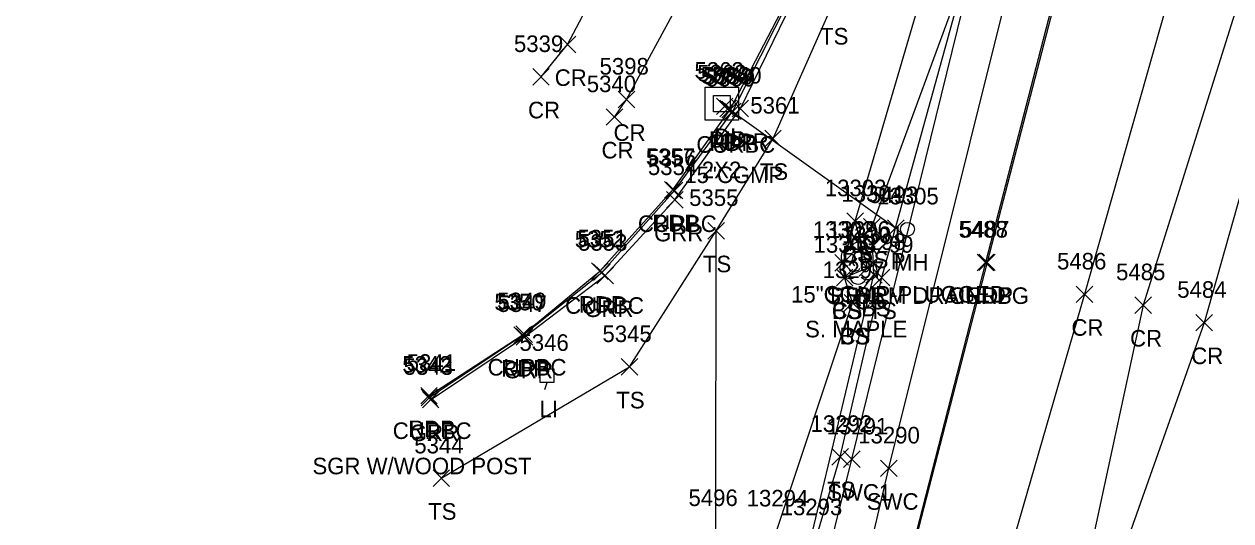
# Model space of a CAD drawing. Extents: x 1462089 to 1464015, y 730534 to 736144.
# Drawn here: x 1462338.4 to 1462484, y 730971.5 to 731031.4 of the extents above; entities that cross this region are included whole.
import ezdxf

# ---------------------------------------------------------------- set-up
doc = ezdxf.new("R2010")
doc.units = 0
for name, color, linetype in [('D_A', 7, 'Continuous'), ('D_C', 7, 'Continuous'), ('D_I', 7, 'Continuous'), ('D_TIC', 7, 'Continuous'), ('DCP', 7, 'Continuous'), ('DS', 7, 'Continuous'), ('L_A', 7, 'Continuous'), ('L_C', 7, 'Continuous'), ('L_I', 7, 'Continuous'), ('L_TIC', 7, 'Continuous'), ('LELB', 7, 'Continuous'), ('LTD', 7, 'Continuous'), ('P_A', 7, 'Continuous'), ('P_I', 7, 'Continuous'), ('P_TIC', 7, 'Continuous'), ('PET', 7, 'Continuous'), ('PRC', 7, 'Continuous'), ('R_A', 7, 'Continuous'), ('R_C', 7, 'Continuous'), ('R_I', 7, 'Continuous'), ('R_TIC', 7, 'Continuous'), ('RC', 7, 'Continuous'), ('RGR', 7, 'Continuous'), ('RSW', 7, 'Continuous'), ('U_A', 7, 'Continuous'), ('U_C', 7, 'Continuous'), ('U_I', 7, 'Continuous'), ('ULP', 7, 'Continuous'), ('UUMH', 7, 'Continuous')]:
    doc.layers.add(name, color=color, linetype=linetype)

msp = doc.modelspace()

# ---------------------------------------------------------------- linework, layer by layer
at = {"layer": 'D_TIC'}
for points in [[(1462421.97, 731020.53), (1462423.97, 731022.53)], [(1462423.97, 731020.53), (1462421.97, 731022.53)], [(1462422.39, 731020.27), (1462424.39, 731022.27)], [(1462424.39, 731020.27), (1462422.39, 731022.27)], [(1462442.63, 731005.85), (1462444.63, 731007.85)], [(1462444.63, 731005.85), (1462442.63, 731007.85)]]:
    msp.add_lwpolyline(points, dxfattribs=at)
at = {"layer": 'DCP'}
msp.add_lwpolyline([(1462423.39, 731021.27), (1462443.63, 731006.85)], dxfattribs=at)
at = {"layer": 'DS'}
for p, q in [((1462420.63, 731023.85), (1462424.63, 731023.85)), ((1462420.63, 731019.85), (1462420.63, 731023.85)), ((1462424.63, 731023.85), (1462424.63, 731019.85)), ((1462421.63, 731020.85), (1462421.63, 731022.85)), ((1462421.63, 731022.85), (1462423.63, 731022.85)), ((1462423.63, 731022.85), (1462423.63, 731020.85)), ((1462423.63, 731020.85), (1462421.63, 731020.85)), ((1462422.63, 731021.86), (1462422.63, 731021.86)), ((1462422.63, 731021.86), (1462422.63, 731021.86)), ((1462424.63, 731019.85), (1462420.63, 731019.85))]:
    msp.add_line(p, q, dxfattribs=at)
at = {"layer": 'L_TIC'}
for points in [[(1462427.8, 731016.65), (1462429.8, 731018.65)], [(1462429.8, 731016.65), (1462427.8, 731018.65)], [(1462437.72, 731006.68), (1462439.72, 731008.68)], [(1462439.72, 731006.68), (1462437.72, 731008.68)], [(1462437.72, 731006.68), (1462439.72, 731008.68)], [(1462439.72, 731006.68), (1462437.72, 731008.68)], [(1462439.72, 731006.01), (1462441.72, 731008.01)], [(1462441.72, 731006.01), (1462439.72, 731008.01)], [(1462420.94, 731005.51), (1462422.94, 731007.51)], [(1462422.94, 731005.51), (1462420.94, 731007.51)], [(1462436.25, 731001.66), (1462438.25, 731003.66)], [(1462438.25, 731001.66), (1462436.25, 731003.66)], [(1462436.44, 730999.87), (1462438.44, 731001.87)], [(1462438.44, 730999.87), (1462436.44, 731001.87)], [(1462436.44, 730999.87), (1462438.44, 731001.87)], [(1462438.44, 730999.87), (1462436.44, 731001.87)], [(1462439.2, 731001.04), (1462441.2, 731003.04)], [(1462441.2, 731001.04), (1462439.2, 731003.04)], [(1462439.98, 731000.2), (1462441.98, 731002.2)], [(1462441.98, 731000.2), (1462439.98, 731002.2)], [(1462439.98, 731000.2), (1462441.98, 731002.2)], [(1462441.98, 731000.2), (1462439.98, 731002.2)], [(1462440.91, 730999.87), (1462442.91, 731001.87)], [(1462442.91, 730999.87), (1462440.91, 731001.87)], [(1462437.38, 730996.81), (1462439.38, 730998.81)], [(1462439.38, 730996.81), (1462437.38, 730998.81)], [(1462437.38, 730996.81), (1462439.38, 730998.81)], [(1462439.38, 730996.81), (1462437.38, 730998.81)], [(1462410.48, 730989.09), (1462412.48, 730991.09)], [(1462412.48, 730989.09), (1462410.48, 730991.09)], [(1462435.91, 730978.25), (1462437.91, 730980.25)], [(1462437.91, 730978.25), (1462435.91, 730980.25)], [(1462387.78, 730975.66), (1462389.78, 730977.66)], [(1462389.78, 730975.66), (1462387.78, 730977.66)]]:
    msp.add_lwpolyline(points, dxfattribs=at)
at = {"layer": 'LELB'}
for points in [[(1462388.78, 730976.66), (1462411.48, 730990.09), (1462421.94, 731006.51), (1462428.8, 731017.65), (1462436.07, 731033.98), (1462445.93, 731054.5), (1462454.8, 731072.36), (1462455.33, 731073.48), (1462460.84, 731086.83), (1462466.01, 731088.73), (1462468.93, 731104.02), (1462472.78, 731103.78), (1462475.18, 731100.17)], [(1462438.38, 730997.81), (1462437.44, 731000.87), (1462440.2, 731002.04), (1462438.72, 731007.68), (1462447.67, 731038.22), (1462450.05, 731039.02), (1462449.7, 731045.42), (1462457.74, 731068.03), (1462468.26, 731085.52), (1462472.82, 731091.07), (1462474.19, 731089.34)], [(1462427.16, 730950.62), (1462433.31, 730969.2), (1462440.98, 731001.2), (1462440.72, 731007.01), (1462452.3, 731038.49), (1462460.27, 731066.27)], [(1462429.66, 730954.76), (1462436.91, 730979.25), (1462441.91, 731000.87), (1462452.3, 731038.49)], [(1462437.44, 731000.87), (1462437.25, 731002.66), (1462438.72, 731007.68)], [(1462421.91, 730970.31), (1462421.94, 731006.51)], [(1462419.91, 730951.53), (1462429.21, 730970.26), (1462438.38, 730997.81), (1462440.98, 731001.2)]]:
    msp.add_lwpolyline(points, dxfattribs=at)
at = {"layer": 'LTD'}
msp.add_line((1462439.09, 731002.66), (1462439.09, 731002.66), dxfattribs=at)
msp.add_line((1462439.09, 731002.66), (1462439.09, 731002.66), dxfattribs=at)
msp.add_arc((1462439.14, 731004.1), 1.05, 335.5272, 180.9563, dxfattribs=at)
for centre, major_axis, ratio, start_param, end_param in [((1462438.3, 731003.33), (1.21, -0.51), 0.895232, 1.570796, 4.712389), ((1462438.88, 731003.12), (-0.208, -0.792), 0.645439, 3.141593, 6.283185), ((1462439.59, 731002.5), (-0.5, 0.667), 0.989748, 3.141593, 6.283185), ((1462440.13, 731003.25), (-1.14, -0.48), 0.949671, 1.570796, 4.712389), ((1462438.01, 731001.95), (0.58, -1.04), 0.959034, 3.141593, 6.283185), ((1462438.63, 731001.91), (-0.625, -0.083), 0.423636, 0, 3.141593), ((1462440.09, 731001.83), (-1.09, 0.79), 0.841452, 1.570796, 4.712389), ((1462439.09, 731001.16), (0.26, 1.06), 0.942809, 1.570796, 4.712389)]:
    msp.add_ellipse(centre, major_axis=major_axis, ratio=ratio, start_param=start_param, end_param=end_param, dxfattribs=at)
at = {"layer": 'P_TIC'}
for points in [[(1462403.02, 731027.99), (1462405.02, 731029.99)], [(1462405.02, 731027.99), (1462403.02, 731029.99)], [(1462399.81, 731024.08), (1462401.81, 731026.08)], [(1462401.81, 731024.08), (1462399.81, 731026.08)], [(1462410.13, 731021.36), (1462412.13, 731023.36)], [(1462412.13, 731021.36), (1462410.13, 731023.36)], [(1462408.68, 731019.24), (1462410.68, 731021.24)], [(1462410.68, 731019.24), (1462408.68, 731021.24)], [(1462422.63, 731020.14), (1462424.63, 731022.14)], [(1462424.63, 731020.14), (1462422.63, 731022.14)], [(1462415.71, 731010.45), (1462417.71, 731012.45)], [(1462417.71, 731010.45), (1462415.71, 731012.45)], [(1462453.62, 731001.71), (1462455.62, 731003.71)], [(1462455.62, 731001.71), (1462453.62, 731003.71)], [(1462406.89, 731000.63), (1462408.89, 731002.63)], [(1462408.89, 731000.63), (1462406.89, 731002.63)], [(1462465.38, 730997.85), (1462467.38, 730999.85)], [(1462467.38, 730997.85), (1462465.38, 730999.85)], [(1462472.45, 730996.55), (1462474.45, 730998.55)], [(1462474.45, 730996.55), (1462472.45, 730998.55)], [(1462479.83, 730994.43), (1462481.83, 730996.43)], [(1462481.83, 730994.43), (1462479.83, 730996.43)], [(1462397.52, 730992.91), (1462399.52, 730994.91)], [(1462399.52, 730992.91), (1462397.52, 730994.91)], [(1462386.29, 730985.62), (1462388.29, 730987.62)], [(1462388.29, 730985.62), (1462386.29, 730987.62)]]:
    msp.add_lwpolyline(points, dxfattribs=at)
at = {"layer": 'PET'}
for points in [[(1462387.29, 730986.62), (1462398.52, 730993.91), (1462407.89, 731001.63), (1462416.71, 731011.45), (1462423.63, 731021.14), (1462432.28, 731037.78), (1462439.01, 731056.63), (1462451.5, 731091.34), (1462455.92, 731100.01), (1462464.31, 731107.07), (1462468.29, 731108.58), (1462472.93, 731107.75)], [(1462468.33, 731055.46), (1462454.62, 731002.71), (1462439.37, 730943.54), (1462426.72, 730893.88), (1462414.13, 730848.03), (1462402.67, 730810.27), (1462391.12, 730771.79), (1462384.96, 730750.7), (1462383.45, 730746.12), (1462378.84, 730730.43)]]:
    msp.add_lwpolyline(points, dxfattribs=at)
at = {"layer": 'PRC'}
for points in [[(1462761.02, 731958.42), (1462747.81, 731917.01), (1462738.76, 731883.17), (1462729.11, 731854.95), (1462715.07, 731806.48), (1462712.12, 731796.98), (1462698.11, 731749.33), (1462686.28, 731711.96), (1462673.04, 731665.23), (1462661.99, 731629.57), (1462648.47, 731585.76), (1462633.36, 731535.92), (1462617.82, 731486.9), (1462603.28, 731439.32), (1462592.21, 731404.81), (1462578.75, 731359.84), (1462563.85, 731311.63), (1462546.16, 731252.05), (1462529.31, 731193.32), (1462512.83, 731138.46), (1462500.46, 731089.18), (1462489.91, 731049.97), (1462473.45, 730997.55), (1462460.79, 730938.78)], [(1462502.24, 731140.65), (1462491.59, 731093.41), (1462481.41, 731051.89), (1462466.38, 730998.85), (1462449.74, 730941.33), (1462438.11, 730890.41), (1462425.45, 730844.2), (1462414.38, 730806.64), (1462401.13, 730755.95), (1462392.12, 730727.26), (1462378.76, 730682.13), (1462374.56, 730668.66), (1462358.3, 730624.57), (1462349.45, 730590.21), (1462338.44, 730561.09)], [(1462522.11, 731136.27), (1462509.01, 731086.5), (1462495.84, 731048.68), (1462480.83, 730995.43), (1462460.79, 730938.78), (1462449.01, 730886.81), (1462435.47, 730841.1), (1462424.6, 730802.23), (1462409.98, 730750.74), (1462401.88, 730724.37), (1462388, 730678.77), (1462384.49, 730666.35), (1462369.1, 730623.58), (1462360.68, 730585), (1462348.49, 730557.7)], [(1462400.81, 731025.08), (1462404.02, 731028.99), (1462414.27, 731048.41), (1462425.15, 731083.36), (1462432.01, 731107.16), (1462441.86, 731124.76)], [(1462409.68, 731020.24), (1462411.13, 731022.36), (1462424.24, 731046.53), (1462435.58, 731081.11), (1462442.07, 731100.85), (1462450.24, 731114.13), (1462458.36, 731120.68), (1462472.22, 731125.09), (1462482.97, 731125.14)]]:
    msp.add_lwpolyline(points, dxfattribs=at)
at = {"layer": 'R_TIC'}
for points in [[(1462423.86, 731020.27), (1462425.86, 731022.27)], [(1462425.86, 731020.27), (1462423.86, 731022.27)], [(1462422.96, 731019.93), (1462424.96, 731021.93)], [(1462424.96, 731019.93), (1462422.96, 731021.93)], [(1462415.92, 731010.37), (1462417.92, 731012.37)], [(1462417.92, 731010.37), (1462415.92, 731012.37)], [(1462415.96, 731009.24), (1462417.96, 731011.24)], [(1462417.96, 731009.24), (1462415.96, 731011.24)], [(1462453.45, 731001.69), (1462455.45, 731003.69)], [(1462455.45, 731001.69), (1462453.45, 731003.69)], [(1462407.14, 731000.5), (1462409.14, 731002.5)], [(1462409.14, 731000.5), (1462407.14, 731002.5)], [(1462407.54, 731000.11), (1462409.54, 731002.11)], [(1462409.54, 731000.11), (1462407.54, 731002.11)], [(1462397.78, 730993.05), (1462399.78, 730995.05)], [(1462399.78, 730993.05), (1462397.78, 730995.05)], [(1462397.82, 730992.72), (1462399.82, 730994.72)], [(1462399.82, 730992.72), (1462397.82, 730994.72)], [(1462386.33, 730985.4), (1462388.33, 730987.4)], [(1462388.33, 730985.4), (1462386.33, 730987.4)], [(1462386.49, 730985.14), (1462388.49, 730987.14)], [(1462388.49, 730985.14), (1462386.49, 730987.14)], [(1462437.3, 730977.95), (1462439.3, 730979.95)], [(1462439.3, 730977.95), (1462437.3, 730979.95)], [(1462441.76, 730976.86), (1462443.76, 730978.86)], [(1462443.76, 730976.86), (1462441.76, 730978.86)]]:
    msp.add_lwpolyline(points, dxfattribs=at)
at = {"layer": 'RC'}
for points in [[(1462387.33, 730986.4), (1462398.78, 730994.05), (1462408.14, 731001.5), (1462416.92, 731011.37), (1462423.96, 731020.93), (1462432.41, 731037.66), (1462439.14, 731056.6), (1462451.82, 731091.25), (1462456.08, 731100.02), (1462464.43, 731106.91), (1462468.29, 731108.1), (1462472.86, 731107.37), (1462472.79, 731107.02)], [(1462468.06, 731055.45), (1462454.45, 731002.69), (1462439.29, 730943.64), (1462426.45, 730893.89), (1462413.94, 730848.16), (1462402.51, 730810.31), (1462391.11, 730771.86), (1462384.6, 730751)]]:
    msp.add_lwpolyline(points, dxfattribs=at)
at = {"layer": 'RGR'}
msp.add_lwpolyline([(1462387.49, 730986.14), (1462398.82, 730993.72), (1462408.54, 731001.11), (1462416.96, 731010.24), (1462424.86, 731021.27), (1462432.73, 731037.41), (1462439.73, 731056.23)], dxfattribs=at)
at = {"layer": 'RSW'}
for points in [[(1462365.21, 730706.59), (1462365.68, 730709.78), (1462367.08, 730715.11), (1462375.58, 730745.47), (1462378.85, 730756.94), (1462385.65, 730780.97), (1462396.44, 730819.68), (1462403.54, 730845.95), (1462401.34, 730846.49), (1462400.76, 730846.71), (1462402.18, 730851.52), (1462402.74, 730851.2), (1462404.92, 730850.63), (1462415.03, 730885.13), (1462424.08, 730920.73), (1462432.26, 730954.61), (1462438.3, 730978.95), (1462452.96, 731038.49), (1462460.27, 731066.27), (1462471.19, 731084.22), (1462474.19, 731089.34), (1462475.99, 731088.66), (1462476.77, 731088.46)], [(1462369.06, 730705.4), (1462369.74, 730708.32), (1462371.3, 730712.9), (1462380.07, 730743.76), (1462383.54, 730755.61), (1462390.33, 730779.63), (1462401.13, 730818.25), (1462408.88, 730846.66), (1462419.31, 730882.83), (1462428.73, 730919.27), (1462437.08, 730953.46), (1462442.76, 730977.86), (1462457.49, 731036.9), (1462465, 731064.86), (1462473.69, 731078.83), (1462474.26, 731078.76), (1462476.77, 731088.46)]]:
    msp.add_lwpolyline(points, dxfattribs=at)
at = {"layer": 'ULP'}
for p, q in [((1462401.69, 730990.7), (1462401.53, 730989.87)), ((1462400.69, 730988.2), (1462400.69, 730989.87)), ((1462400.69, 730989.87), (1462402.36, 730989.87)), ((1462401.53, 730989.03), (1462401.53, 730989.03)), ((1462402.36, 730989.87), (1462402.36, 730988.2)), ((1462402.36, 730988.2), (1462400.69, 730988.2)), ((1462401.28, 730987.37), (1462401.53, 730988.2))]:
    msp.add_line(p, q, dxfattribs=at)
at = {"layer": 'UUMH'}
for p, q in [((1462445.03, 731006.7), (1462445.03, 731006.7)), ((1462445.87, 731006.7), (1462445.87, 731006.7))]:
    msp.add_line(p, q, dxfattribs=at)
msp.add_circle((1462445.03, 731006.7), 0.833, dxfattribs=at)

# ---------------------------------------------------------------- texts
at = {"layer": 'D_A'}
for s, p in [('DIB', (1462421.07, 731016.53)), ('DI', (1462421.69, 731016.86)), ('P', (1462422.77, 731016.27)), ('P', (1462443.01, 731001.85))]:
    msp.add_text(s, height=2, dxfattribs=at).set_placement(p)
at = {"layer": 'D_C'}
for s, p in [('15"CGMP', (1462418.1, 731012.27)), ('2X2', (1462420.21, 731012.86)), ('15"CGMP-PLUGGED', (1462430.98, 730997.85))]:
    msp.add_text(s, height=2, dxfattribs=at).set_placement(p)
at = {"layer": 'D_I'}
for s, p in [('5362', (1462419.32, 731024.86)), ('5363', (1462419.66, 731024.53)), ('5364', (1462420.09, 731024.27)), ('5493', (1462440.37, 731009.85))]:
    msp.add_text(s, height=2, dxfattribs=at).set_placement(p)
at = {"layer": 'L_A'}
for s, p in [('TS', (1462434.48, 731028.98)), ('TS', (1462427.21, 731012.65)), ('TS', (1462420.34, 731001.51)), ('CS', (1462437.16, 731002.68)), ('BS', (1462437.16, 731002.68)), ('BS', (1462439.16, 731002.01)), ('BS', (1462435.7, 730997.66)), ('H', (1462438.52, 730997.66)), ('CS', (1462438.64, 730997.04)), ('CS', (1462435.88, 730995.87)), ('BS', (1462435.88, 730995.87)), ('BS', (1462439.42, 730996.2)), ('BS', (1462439.42, 730996.2)), ('TS', (1462440.32, 730995.87)), ('CS', (1462436.83, 730992.81)), ('BS', (1462436.83, 730992.81)), ('TS', (1462409.89, 730985.09)), ('TS', (1462435.32, 730974.25)), ('TS', (1462387.19, 730971.66))]:
    msp.add_text(s, height=2, dxfattribs=at).set_placement(p)
at = {"layer": 'L_C'}
msp.add_text('S. MAPLE', height=2, dxfattribs=at).set_placement((1462432.67, 730993.66))
at = {"layer": 'L_I'}
for s, p in [('5361', (1462426.06, 731020.65)), ('13303', (1462435.05, 731010.68)), ('13303', (1462435.05, 731010.68)), ('13304', (1462437.05, 731010.01)), ('5355', (1462418.68, 731009.51)), ('13302', (1462433.59, 731005.66)), ('13296', (1462435.45, 731005.66)), ('13301', (1462437.1, 731005.04)), ('13298', (1462437.39, 731004.2)), ('13298', (1462437.39, 731004.2)), ('13300', (1462433.69, 731003.87)), ('13300', (1462433.69, 731003.87)), ('13299', (1462438.31, 731003.87)), ('13297', (1462434.79, 731000.81)), ('13297', (1462434.79, 731000.81)), ('5345', (1462408.22, 730993.09)), ('13292', (1462433.32, 730982.25)), ('5344', (1462385.52, 730979.66)), ('5496', (1462418.6, 730973.31)), ('13294', (1462425.62, 730973.26)), ('13293', (1462429.72, 730972.2))]:
    msp.add_text(s, height=2, dxfattribs=at).set_placement(p)
at = {"layer": 'P_A'}
for s, p in [('CR', (1462402.46, 731023.99)), ('CR', (1462399.24, 731020.08)), ('CR', (1462409.56, 731017.36)), ('RDP', (1462421.12, 731016.14)), ('CR', (1462408.11, 731015.24)), ('RDP', (1462414.2, 731006.45)), ('RDP', (1462452.11, 730997.71)), ('RDP', (1462405.38, 730996.63)), ('CR', (1462464.81, 730993.85)), ('CR', (1462471.88, 730992.55)), ('CR', (1462479.26, 730990.43)), ('RDP', (1462396.01, 730988.91)), ('RDP', (1462384.78, 730981.62))]:
    msp.add_text(s, height=2, dxfattribs=at).set_placement(p)
at = {"layer": 'P_I'}
for s, p in [('5339', (1462397.54, 731028.08)), ('5398', (1462407.87, 731025.36)), ('5340', (1462406.33, 731023.24)), ('5358', (1462420.37, 731024.14)), ('5357', (1462413.45, 731014.45)), ('5487', (1462451.36, 731005.71)), ('5351', (1462405.2, 731004.63)), ('5486', (1462463.07, 731001.85)), ('5485', (1462470.19, 731000.55)), ('5484', (1462477.57, 730998.43)), ('5350', (1462395.18, 730996.91)), ('5341', (1462384.6, 730989.62))]:
    msp.add_text(s, height=2, dxfattribs=at).set_placement(p)
at = {"layer": 'R_A'}
for s, p in [('CURBC', (1462419.55, 731015.93)), ('GRR', (1462422.35, 731016.27)), ('CURBC', (1462412.5, 731006.37)), ('GRR', (1462414.45, 731005.24)), ('CURBG', (1462450.03, 730997.69)), ('CURBC', (1462403.72, 730996.5)), ('GRR', (1462406.02, 730996.11)), ('CURBC', (1462394.37, 730989.05)), ('GRR', (1462396.3, 730988.72)), ('CURBC', (1462382.92, 730981.4)), ('GRR', (1462384.98, 730981.14)), ('SWC1', (1462435.34, 730973.95)), ('SWC', (1462440.12, 730972.86))]:
    msp.add_text(s, height=2, dxfattribs=at).set_placement(p)
at = {"layer": 'R_C'}
msp.add_text('SGR W/WOOD POST', height=2, dxfattribs=at).set_placement((1462373.23, 730977.14))
at = {"layer": 'R_I'}
for s, p in [('5359', (1462420.7, 731023.93)), ('5360', (1462421.47, 731024.27)), ('5356', (1462413.6, 731014.37)), ('5354', (1462413.7, 731013.24)), ('5488', (1462451.19, 731005.69)), ('5352', (1462404.88, 731004.5)), ('5353', (1462405.28, 731004.11)), ('5349', (1462395.52, 730997.05)), ('5347', (1462395.56, 730996.72)), ('5342', (1462384.07, 730989.4)), ('5343', (1462384.23, 730989.14)), ('13291', (1462435.27, 730981.95)), ('13290', (1462439.08, 730980.86))]:
    msp.add_text(s, height=2, dxfattribs=at).set_placement(p)
at = {"layer": 'U_A'}
for s, p in [('MH', (1462443.39, 731001.7)), ('LI', (1462400.63, 730984.03))]:
    msp.add_text(s, height=2, dxfattribs=at).set_placement(p)
at = {"layer": 'U_C'}
msp.add_text('STORM DRAIN', height=2, dxfattribs=at).set_placement((1462435.23, 730997.7))
at = {"layer": 'U_I'}
for s, p in [('13305', (1462441.36, 731009.7)), ('5346', (1462398.21, 730992.03))]:
    msp.add_text(s, height=2, dxfattribs=at).set_placement(p)

doc.saveas('drawing.dxf')
